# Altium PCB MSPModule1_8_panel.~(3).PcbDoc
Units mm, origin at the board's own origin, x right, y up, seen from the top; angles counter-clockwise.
Board outline 152.4 x 101.6 mm, 2 copper layers (Top Layer, Bottom Layer); 0 components, 0 nets, 0 pads, 0 vias.
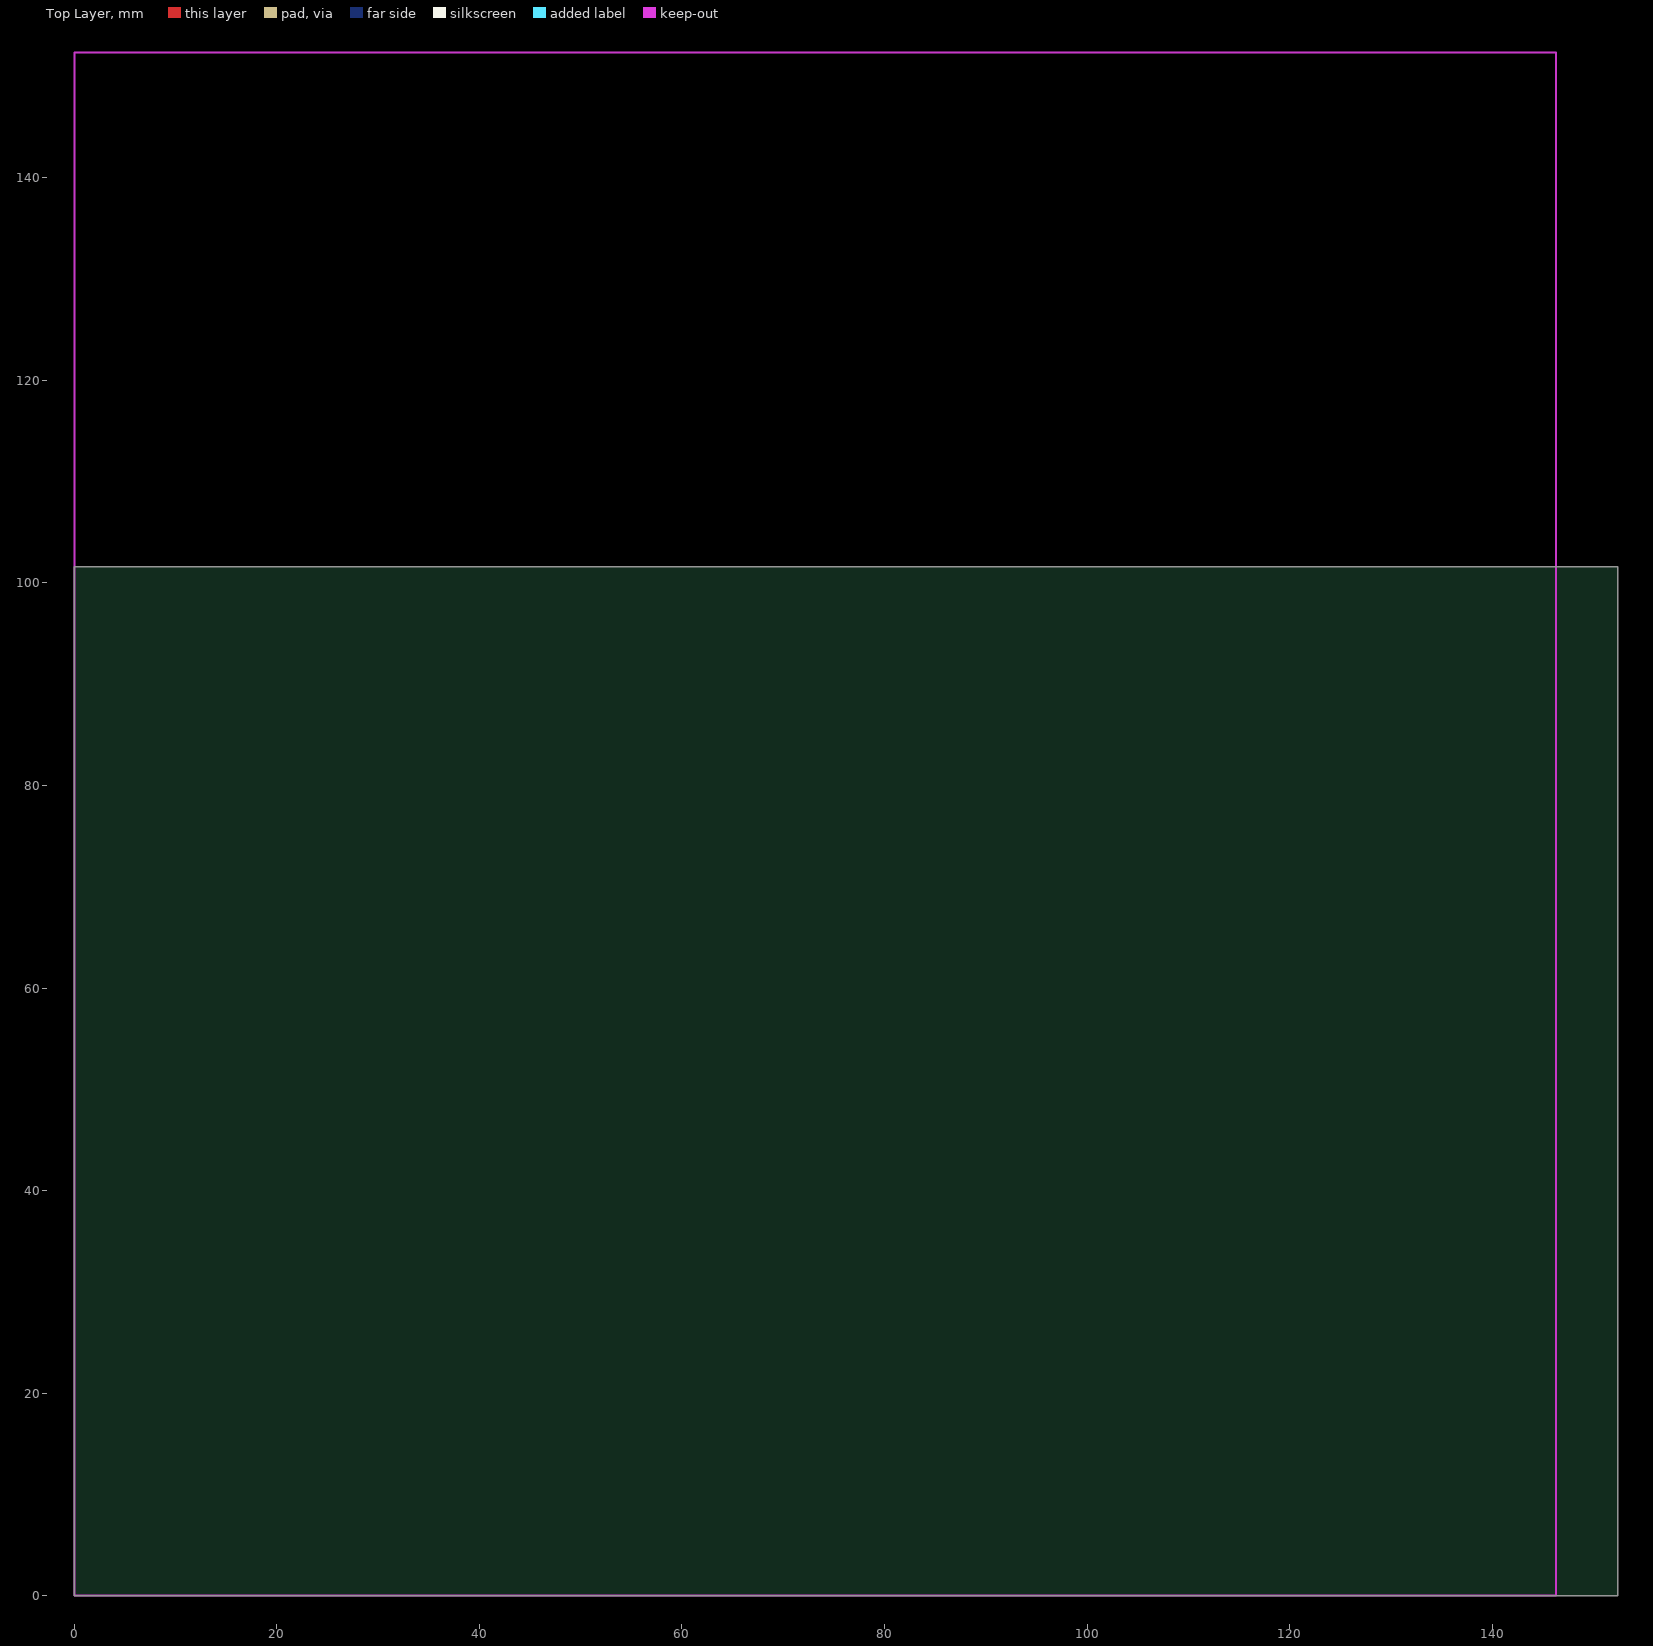
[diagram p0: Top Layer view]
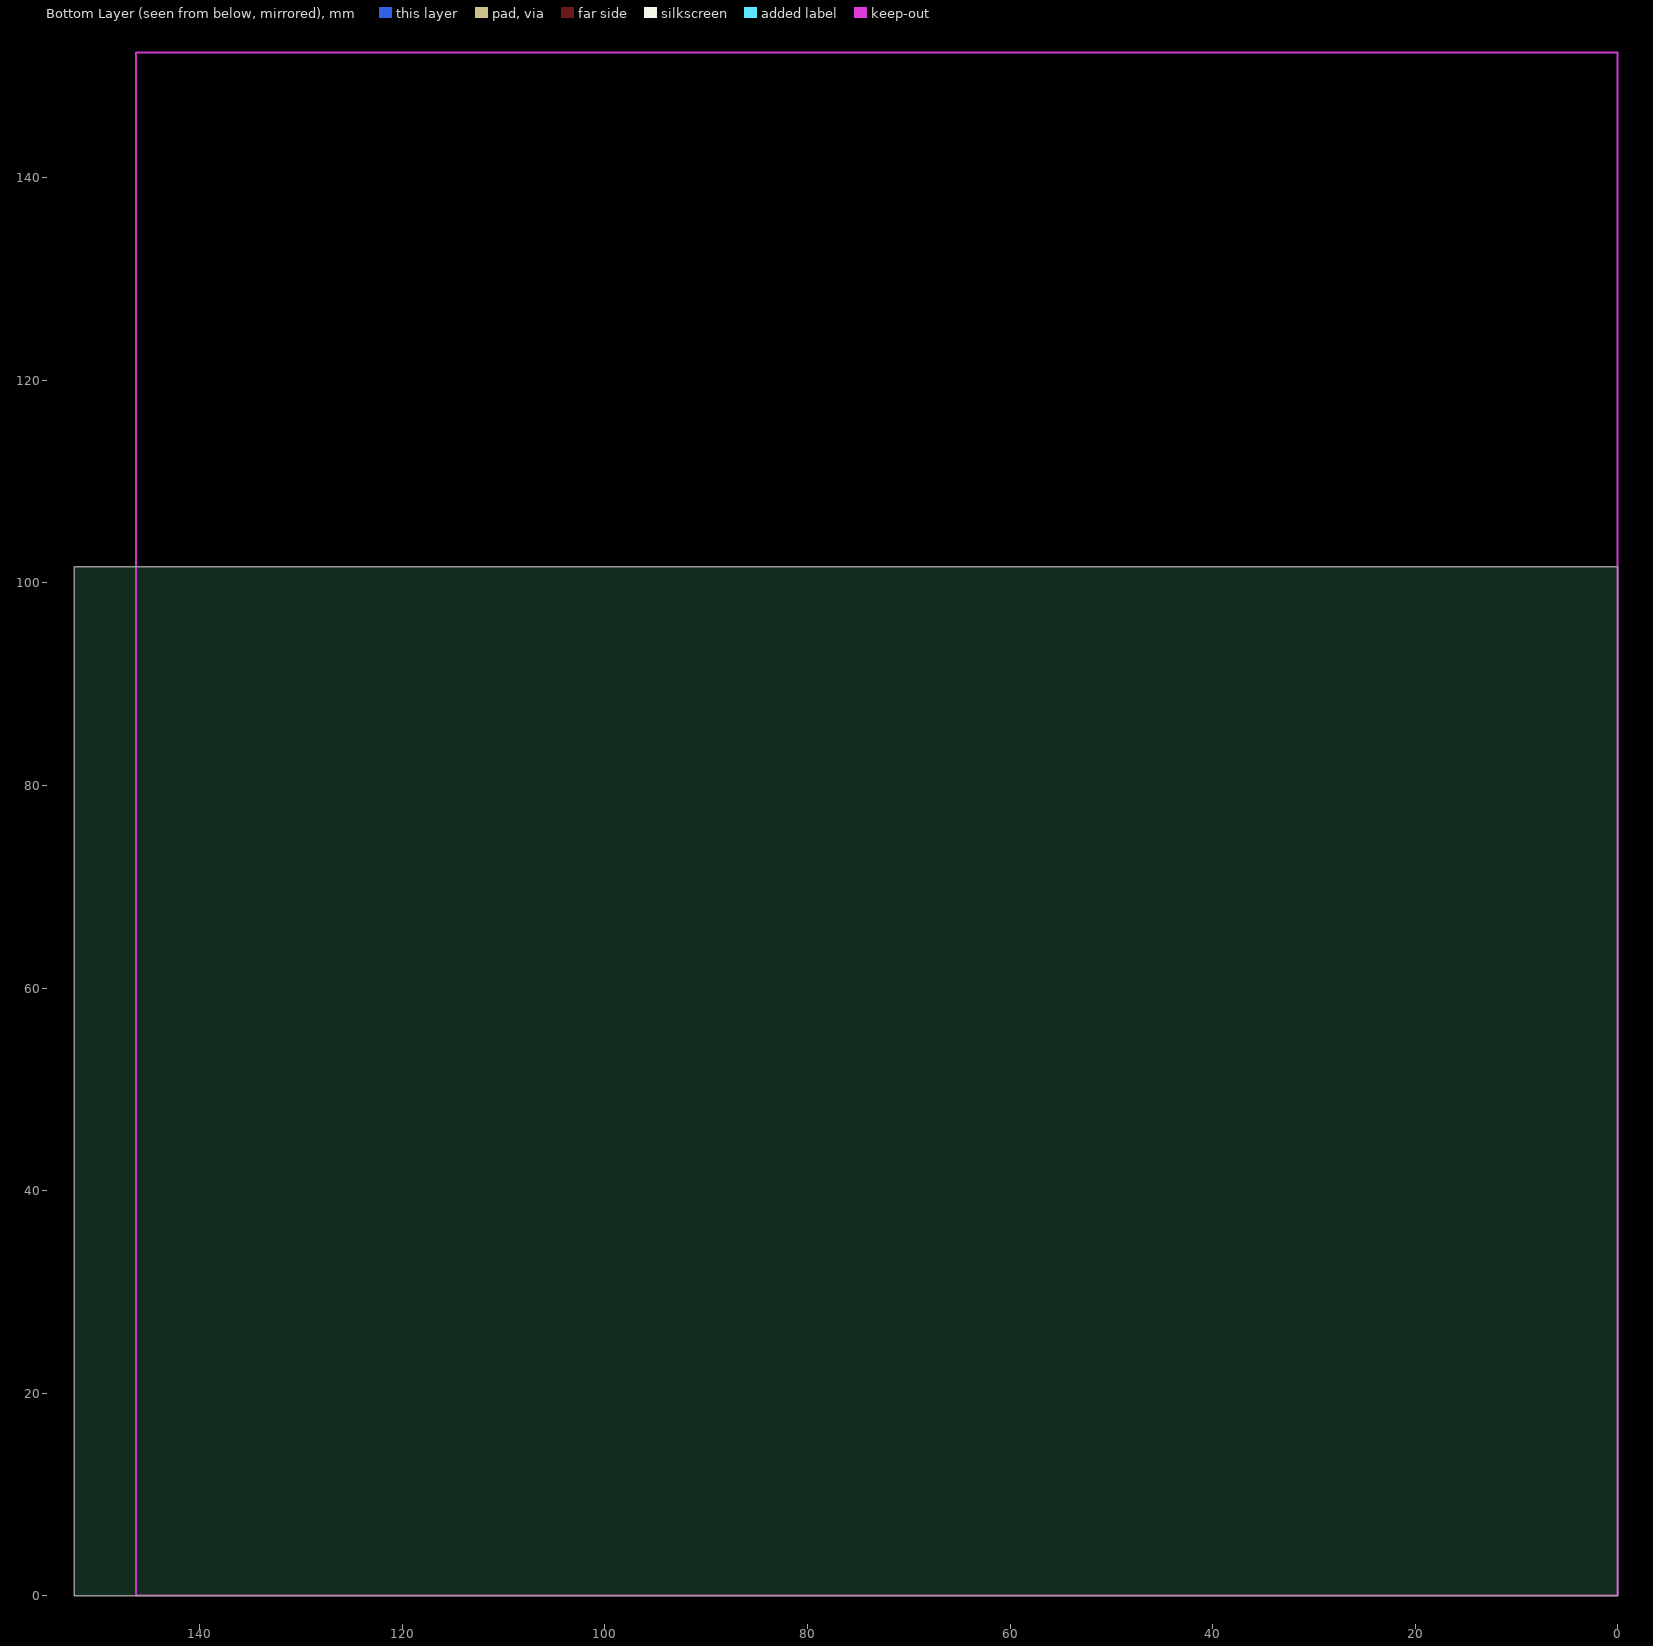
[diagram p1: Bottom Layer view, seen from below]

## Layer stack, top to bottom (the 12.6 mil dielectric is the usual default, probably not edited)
Top Solder: solder mask 0.0102, Solder Resist, Dk 3.5
Top Layer: signal copper 0.0356
Dielectric 1: dielectric 0.32, FR-4, Dk 4.8
Bottom Layer: signal copper 0.0356
Bottom Solder: solder mask 0.0102, Solder Resist, Dk 3.5

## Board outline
0,0 152.4,0 152.4,101.6 0,101.6

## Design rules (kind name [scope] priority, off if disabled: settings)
Clearance [All] p1: gap=0.254 ignorepadtopadclearanceinfootprint=FALSE except(0: Arc-Hole Track-Hole SMDPad-Hole THPad-Hole Via-Hole Fill-Hole Poly-Hole Region-Hole Text-Hole)
PolygonConnect [All] p1: connectstyle=Relief reliefconductorwidth=0.254 reliefentries=4 polygonreliefangle="90 Angle" airgapwidth=0.254
RoutingVias [All] p1: holewidth=0.711 width=1.27 viastyle="Through Hole" minholewidth=0.711 minwidth=1.27 maxholewidth=0.711 maxwidth=1.27
SolderMaskExpansion [All] p1: expansion=0.102
Width [All] p1: maxlimit=0.254 minlimit=0.254 preferedwidth=0.254
30 further rules are at their usual default settings.

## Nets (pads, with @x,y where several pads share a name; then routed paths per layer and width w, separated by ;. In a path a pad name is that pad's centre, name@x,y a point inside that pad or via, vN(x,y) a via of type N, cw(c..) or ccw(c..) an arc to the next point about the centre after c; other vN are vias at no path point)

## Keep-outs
Keep-Out Layer:
  lines w0.2: 0,152.4 0,0 146.304,0 146.304,152.4 0.025,152.4

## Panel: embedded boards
"MSPModule1_8.PcbDoc" at 146.304,0, 4 rows x 3 columns, spacing 36.576 x 50.8, rotation 90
